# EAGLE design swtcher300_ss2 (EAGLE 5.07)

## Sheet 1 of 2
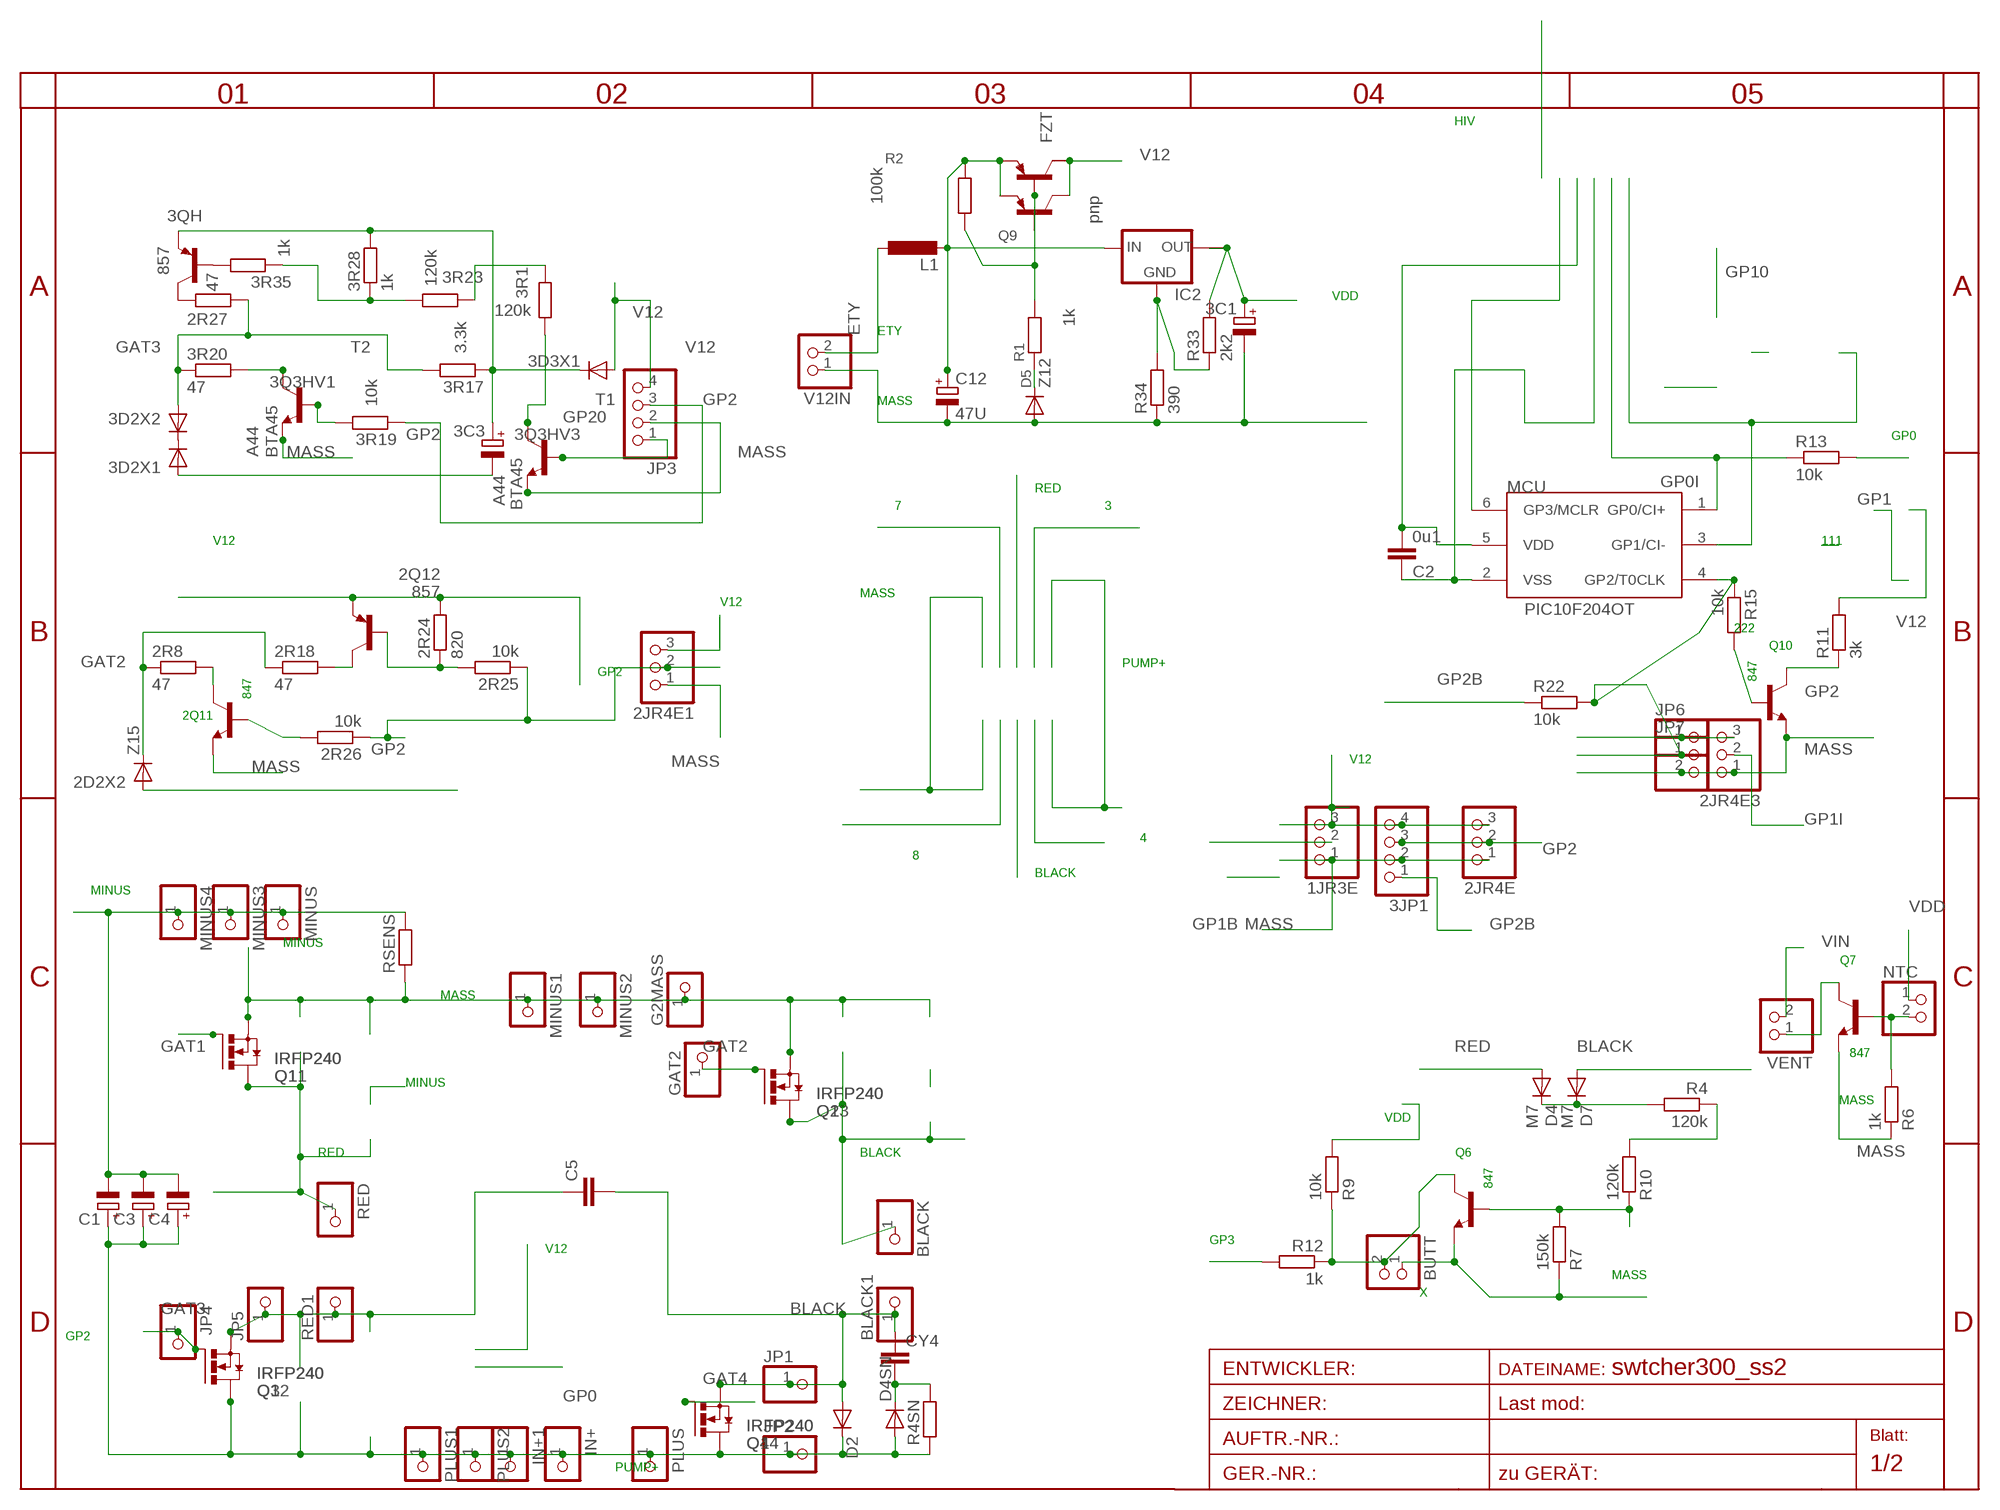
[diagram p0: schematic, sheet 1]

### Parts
1JR3E  PINHD-1X3  [1X03]
2D2X2  Z15  DIODE-MINIMELF  [MINIMELF]
2JR4E  PINHD-1X3  [1X03]
2JR4E1  PINHD-1X3  [1X03]
2JR4E3  PINHD-1X3  [1X03]
2Q11  847  BC847ALT1SMD  [SOT23]
2Q12  857  BC857ALT1SMD  [SOT23-BEC]
2R8  47  R-EU_R0805  [R0805]
2R18  47  R-EU_R0805  [R0805]
2R24  820  R-EU_R0805  [R0805]
2R25  10k  R-EU_R1206  [R1206]
2R26  10k  R-EU_R0805  [R0805]
2R27  47  R-EU_R0805  [R0805]
3C1  CPOL-EUD  [PANASONIC_D]
3C3  CPOL-EUD  [PANASONIC_D]
3D2X1  DIODE-MINIMELF  [MINIMELF]
3D2X2  DIODE-MINIMELF  [MINIMELF]
3D3X1  DIODE-SMA-DO214  [SMA-DO214AC]
3JP1  PINHD-1X4  [1X04]
3Q3HV1  BTA45  SMBTA45HV  [SOT23HV]
3Q3HV3  BTA45  SMBTA45HV  [SOT23HV]
3QH  857  BC857ALT1SMD  [SOT23-BEC]
3R1  120k  R-EU_R1206  [R1206]
3R17  3.3k  R-EU_R1206  [R1206]
3R19  10k  R-EU_R1206  [R1206]
3R20  47  R-EU_0207/10  [0207/10]
3R23  120k  R-EU_R1206  [R1206]
3R28  1k  R-EU_R0805  [R0805]
3R35  1k  R-EU_R0805  [R0805]
BLACK  PINHD-1X12MM3  [1X2MM3]
BLACK1  PINHD-1X12MM3  [1X2MM3]
BUTT  PINHD-1X2STR  [1X02]
C1  CPOL-EUE5-13  [E5-13]
C2  0u1  C-EUC0805  [C0805]
C3  CPOL-EUE5-13  [E5-13]
C4  CPOL-EUE5-13  [E5-13]
C5  C-EU075-032X103  [C075-032X103]
C12  47U  CPOL-EUSMCA  [SMC_A]
CY4  CXXC10B5  [XC10B5]
D2  DIODE-SMC  [SMC]
D4  M7  1N4004DO41-10  [DO41-10]
D4SN  DIODE-P1-10  [P1-10]
D5  Z12  DIODE-MINIMELF  [MINIMELF]
D7  M7  1N4004DO41-10  [DO41-10]
FZT  FZT  FZT753SMD  [SOT223]
G2MASS  PINHD-1X11MM0  [1X1MM0]
GAT2  PINHD-1X11MM0  [1X1MM0]
IC2  AP1117  [SOT223]
IN+  PINHD-1X12MM3  [1X2MM3]
IN+1  PINHD-1X12MM3  [1X2MM3]
JP1  PINHD-1X11MM0  [1X1MM0]
JP2  PINHD-1X11MM0  [1X1MM0]
JP3  PINHD-1X4  [1X04]
JP4  PINHD-1X11MM0  [1X1MM0]
JP5  PINHD-1X11MM0  [1X1MM0]
JP6  PINHD-1X11X0.4  [1X01]
JP7  PINHD-1X2STR  [1X02]
L1  L-EU0204/5  [0204/5]
MCU  PIC10F204OT  [SOT23-6]
MINUS  PINHD-1X12MM3  [1X2MM3]
MINUS1  PINHD-1X12MM3  [1X2MM3]
MINUS2  PINHD-1X12MM3  [1X2MM3]
MINUS3  PINHD-1X12MM3  [1X2MM3]
MINUS4  PINHD-1X12MM3  [1X2MM3]
NTC  PINHD-1X2STR  [1X02]
PLUS  PINHD-1X12MM3  [1X2MM3]
PLUS1  PINHD-1X12MM3  [1X2MM3]
PLUS2  PINHD-1X12MM3  [1X2MM3]
Q1  IRFP240  [TO247BV]
Q2  IRFP240  [TO247BV]
Q3  IRFP240  [TO247BV]
Q4  IRFP240  [TO247BV]
Q6  847  BC847ALT1SMD  [SOT23]
Q7  847  BC847ALT1SMD  [SOT23]
Q9  pnp  BC857ALT1SMD  [SOT23-BEC]
Q10  847  BC847ALT1SMD  [SOT23]
Q11  IRFP240  [TO247BV]
Q12  IRFP240  [TO247BV]
Q13  IRFP240  [TO247BV]
Q14  IRFP240  [TO247BV]
R1  1k  R-EU_R0805  [R0805]
R2  100k  R-EU_R0805  [R0805]
R4  120k  R-EU_R1210  [R1210]
R4SN  R-EU_0207/10  [0207/10]
R6  1k  R-EU_R0805  [R0805]
R7  150k  R-EU_R0805  [R0805]
R9  10k  R-EU_R0805  [R0805]
R10  120k  R-EU_R1210  [R1210]
R11  3k  R-EU_R0805  [R0805]
R12  1k  R-EU_R0805  [R0805]
R13  10k  R-EU_R0805  [R0805]
R15  10k  R-EU_R0805  [R0805]
R22  10k  R-EU_R1206  [R1206]
R33  2k2  R-EU_R0805  [R0805]
R34  390  R-EU_R0805  [R0805]
RED  PINHD-1X12MM3  [1X2MM3]
RED1  PINHD-1X12MM3  [1X2MM3]
RSENS  R-EU_0204/7  [0204/7]
T1  A44  2N2222-NPN-TO92-EBC  [TO92-EBC]
T2  A44  2N2222-NPN-TO92-EBC  [TO92-EBC]
V12IN  PINHD-1X2STR  [1X02]
VENT  PINHD-1X2STR  [1X02]

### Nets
222: Q10.1(B) R15.2
BLACK: BLACK1.1 BLACK.1 C5.2 CY4.1 D2.A D7.A JP1.1 Q2.D Q4.S Q13.D Q14.S
BTRAP+: 3C3.+ 3D3X1.K(C) 3QH.E 3R17.1 3R28.2
ETY: L1.1 V12IN.2
GAT1: Q1.G Q11.G
GAT2: 2D2X2.C 2R8.1 2R18.1 GAT2.1 Q2.G Q13.G
GAT3: 2R27.2 3D2X2.A 3R17.2 3R20.1 JP4.1 Q3.G Q12.G
GAT4: Q4.G Q14.G
GP0: R13.2
GP0I: MCU.1(GP0/CI+) R13.1 ; also sheet 2
GP1I: 2JR4E3.2 MCU.3(GP1/CI-) ; also sheet 2
GP2: 2JR4E1.2 2JR4E.2 2R25.1 2R26.1 3JP1.3 3R19.1 JP3.3 Q10.3(C) R11.1
GP2B: 3JP1.1 3Q3HV3.1(B) JP3.1 R22.1 T1.B
GP2I: 1JR3E.2 JP7.1 MCU.4(GP2/T0CLK) R15.1 R22.2 ; also sheet 2
GP3: MCU.6(GP3/MCLR) R12.2 ; also sheet 2
GP20: 3Q3HV3.3(C) 3R1.1 T1.C
HVC1: 3Q3HV1.3(C) 3R20.2 T2.C
MASS: 1JR3E.1 2D2X2.A 2JR4E1.1 2JR4E3.1 2JR4E.1 2Q11.2(E) 3C1.- 3JP1.2 3Q3HV1.2(E) 3Q3HV3.2(E) BUTT.1 C2.1 C12.- D5.A G2MASS.1 JP3.2 JP7.2 MCU.2(VSS) MINUS1.1 MINUS2.1 Q1.S Q2.S Q6.2(E) Q7.2(E) Q10.2(E) Q11.S Q13.S R6.1 R7.1 R34.1 RSENS.1 T1.E T2.E V12IN.1 ; also sheet 2
MINUS: C1.- C3.- C4.- MINUS3.1 MINUS4.1 MINUS.1 RSENS.2
N$1: D4.C D7.C R4.2
N$2: FZT.1(B) Q9.B R1.2 R2.1
N$3: D5.C R1.1
N$4: 2Q11.3(C) 2R8.2
N$5: Q6.1(B) R7.2 R10.1
N$6: 2Q12.B 2R24.1 2R25.2
N$7: R4.1 R10.2
N$8: 2Q12.C 2R18.2
N$9: NTC.2 Q7.1(B) R6.2
N$10: Q7.3(C) VENT.1
N$11: 3R1.2 3R23.2
N$12: 3Q3HV1.1(B) 3R19.2 T2.B
N$13: 2R27.1 3QH.C
N$17: 3QH.B 3R35.2
N$18: 3R23.1 3R28.1 3R35.1
N$21: 3D2X1.C 3D2X2.C
N$22: 2Q11.1(B) 2R26.2
N$30: IC2.1(GND) R33.1 R34.2
PUMP+: C1.+ C3.+ C4.+ D2.C D4SN.A IN+1.1 IN+.1 JP2.1 PLUS1.1 PLUS2.1 PLUS.1 Q3.D Q4.D Q12.D Q14.D R4SN.1 ; also sheet 2
RED: 3C3.- 3D2X1.A C5.1 D4.A JP5.1 Q1.D Q3.S Q11.D Q12.S RED1.1 RED.1
SNUB2: CY4.2 D4SN.C R4SN.2
V12: 1JR3E.3 2JR4E1.3 2JR4E3.3 2JR4E.3 2Q12.E 2R24.2 3D3X1.A 3JP1.4 FZT.2(C) JP3.4 JP6.1 Q9.C R11.2
VDD: 3C1.+ C2.2 IC2.2(OUT) IC2.4(TAB) MCU.5(VDD) NTC.1 R9.2 R33.2 ; also sheet 2
VIN: C12.+ FZT.3(E) IC2.3(IN) L1.2 Q9.E R2.2 VENT.2
X: BUTT.2 Q6.3(C) R9.1 R12.1
Unconnected: FZT.4(C/)

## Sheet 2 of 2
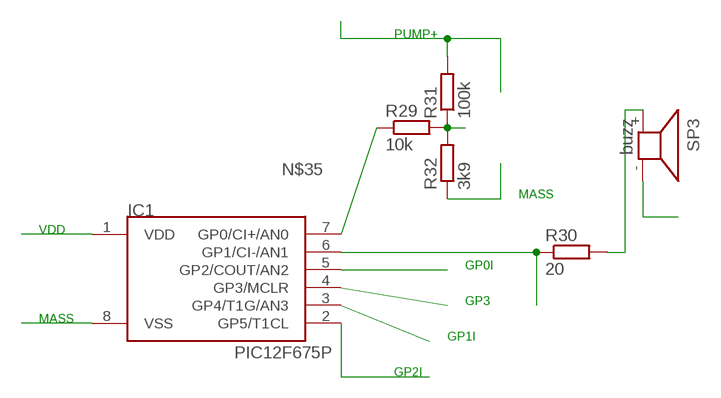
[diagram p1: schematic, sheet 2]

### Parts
IC1  PIC12F675P  [DIL8]
R29  10k  R-EU_R0805  [R0805]
R30  20  R-EU_R0805  [R0805]
R31  100k  R-EU_0207/25  [0207/25]
R32  3k9  R-EU_R0805  [R0805]
SP3  buzz  KSS12017MM  [KSS1202]

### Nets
GP0I: IC1.5(GP2/COUT/AN2) ; also sheet 1
GP1I: IC1.3(GP4/T1G/AN3) ; also sheet 1
GP2I: IC1.2(GP5/T1CL) ; also sheet 1
GP3: IC1.4(GP3/MCLR) ; also sheet 1
MASS: IC1.8(VSS) R32.1 SP3.- ; also sheet 1
N$24: R30.2 SP3.+
N$31: IC1.6(GP1/CI-/AN1) R30.1
N$34: R29.2 R31.1 R32.2
N$35: IC1.7(GP0/CI+/AN0) R29.1
PUMP+: R31.2 ; also sheet 1
VDD: IC1.1(VDD) ; also sheet 1

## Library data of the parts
1JR3E 2JR4E 2JR4E1 2JR4E3 = pinhead:PINHD-1X3: PIN HEADER
2D2X2 3D2X1 3D2X2 3D3X1 D2 D4SN D5 = diode:DIODE-: DIODE
2Q11 Q6 Q7 Q10 = transistor-npn:BC847*: NPN Transistor
2Q12 3QH Q9 = transistor-pnp:BC857*: PNP Transistror
2R8 2R18 2R24-2R27 3R1 3R17 3R19 3R20 3R23 3R28 3R35 R4 R4SN R6 R7 R9 R10 R12 RSENS = rcl:R-EU_: RESISTOR, European symbol
3C1 3C3 C1 C3 C4 = rcl:CPOL-EU: POLARIZED CAPACITOR, European symbol
3JP1 JP3 = pinhead:PINHD-1X4: PIN HEADER
3Q3HV1 3Q3HV3 = transistor-npn:SMBTA45
BLACK BLACK1 G2MASS GAT2 IN+ IN+1 JP1 JP2 JP4-JP6 MINUS MINUS1-MINUS4 PLUS PLUS1 PLUS2 RED RED1 = pinhead:PINHD-1X1: PIN HEADER
BUTT JP7 NTC V12IN VENT = pinhead:PINHD-1X2: PIN HEADER
C2 C5 = rcl:C-EU: CAPACITOR, European symbol
C12 = rcl-2:CPOL-EU: POLARIZED CAPACITOR, European symbol
CY4 = rcl:CX: X CAPACITOR
D4 D7 = diode:1N4004: DIODE
FZT = transistor-pnp:FZT753SMD: PNP Transistor
IC1 = microchip-5:PIC12F6*: uPC nW 1k Program Flash memory 2x Timer Comparator 10b A/D converter/ 4xIN
IC2 = v-reg:AP1117
L1 = rcl:L-EU: INDUCTOR, European symbol
MCU = microchip-3:PIC10F2*: uPC nW 0,25/0,5k Program Flash memory Comparator
Q1-Q4 Q11-Q14 = transistor-power:IRFP240: HEXFET Power MosFet Source: http://www.irf.com/
R1 R2 R11 R13 R15 R22 R29-R34 = rcl-2:R-EU_: RESISTOR, European symbol
SP3 = buzzer:KSS1201: SPEAKER
T1 T2 = transistor-neu-to92:*-NPN-: NPN Transistror

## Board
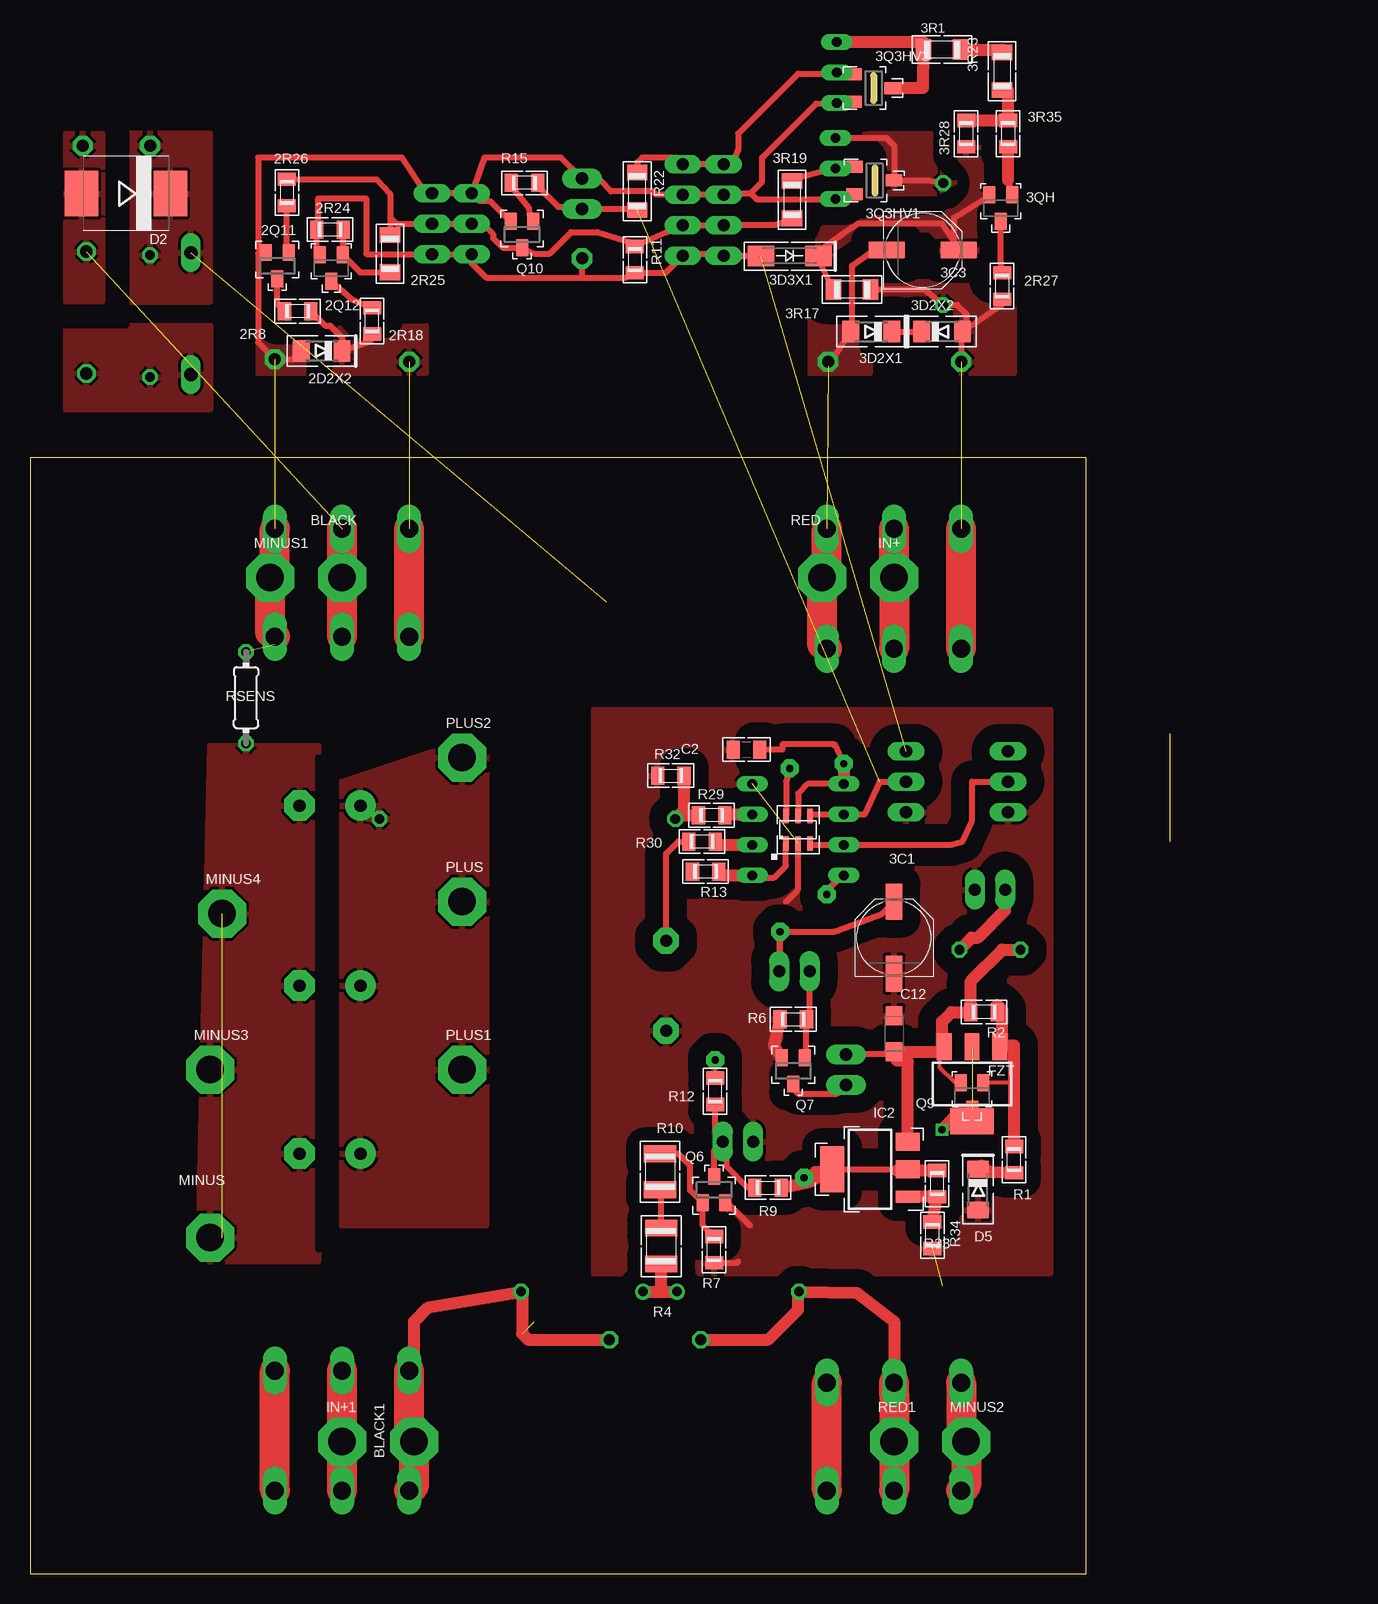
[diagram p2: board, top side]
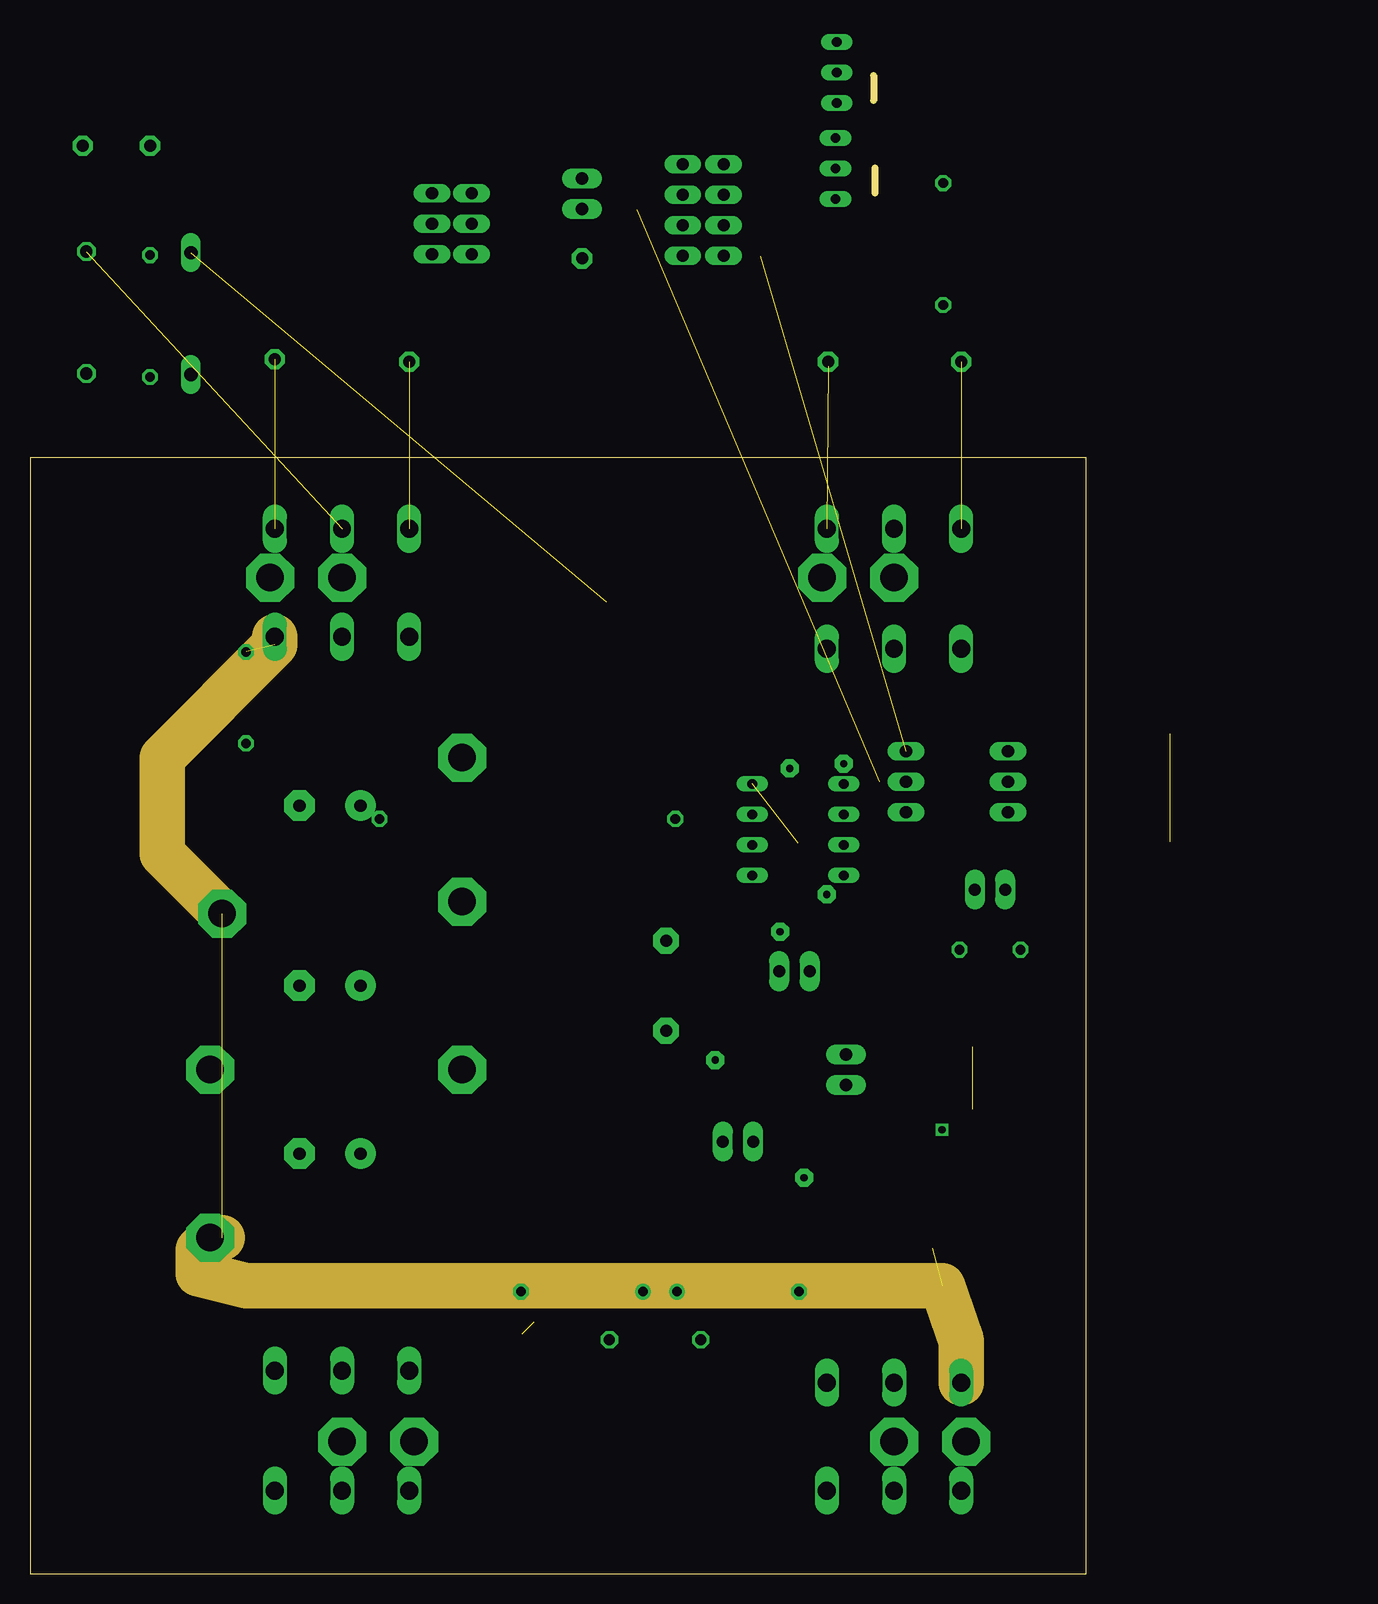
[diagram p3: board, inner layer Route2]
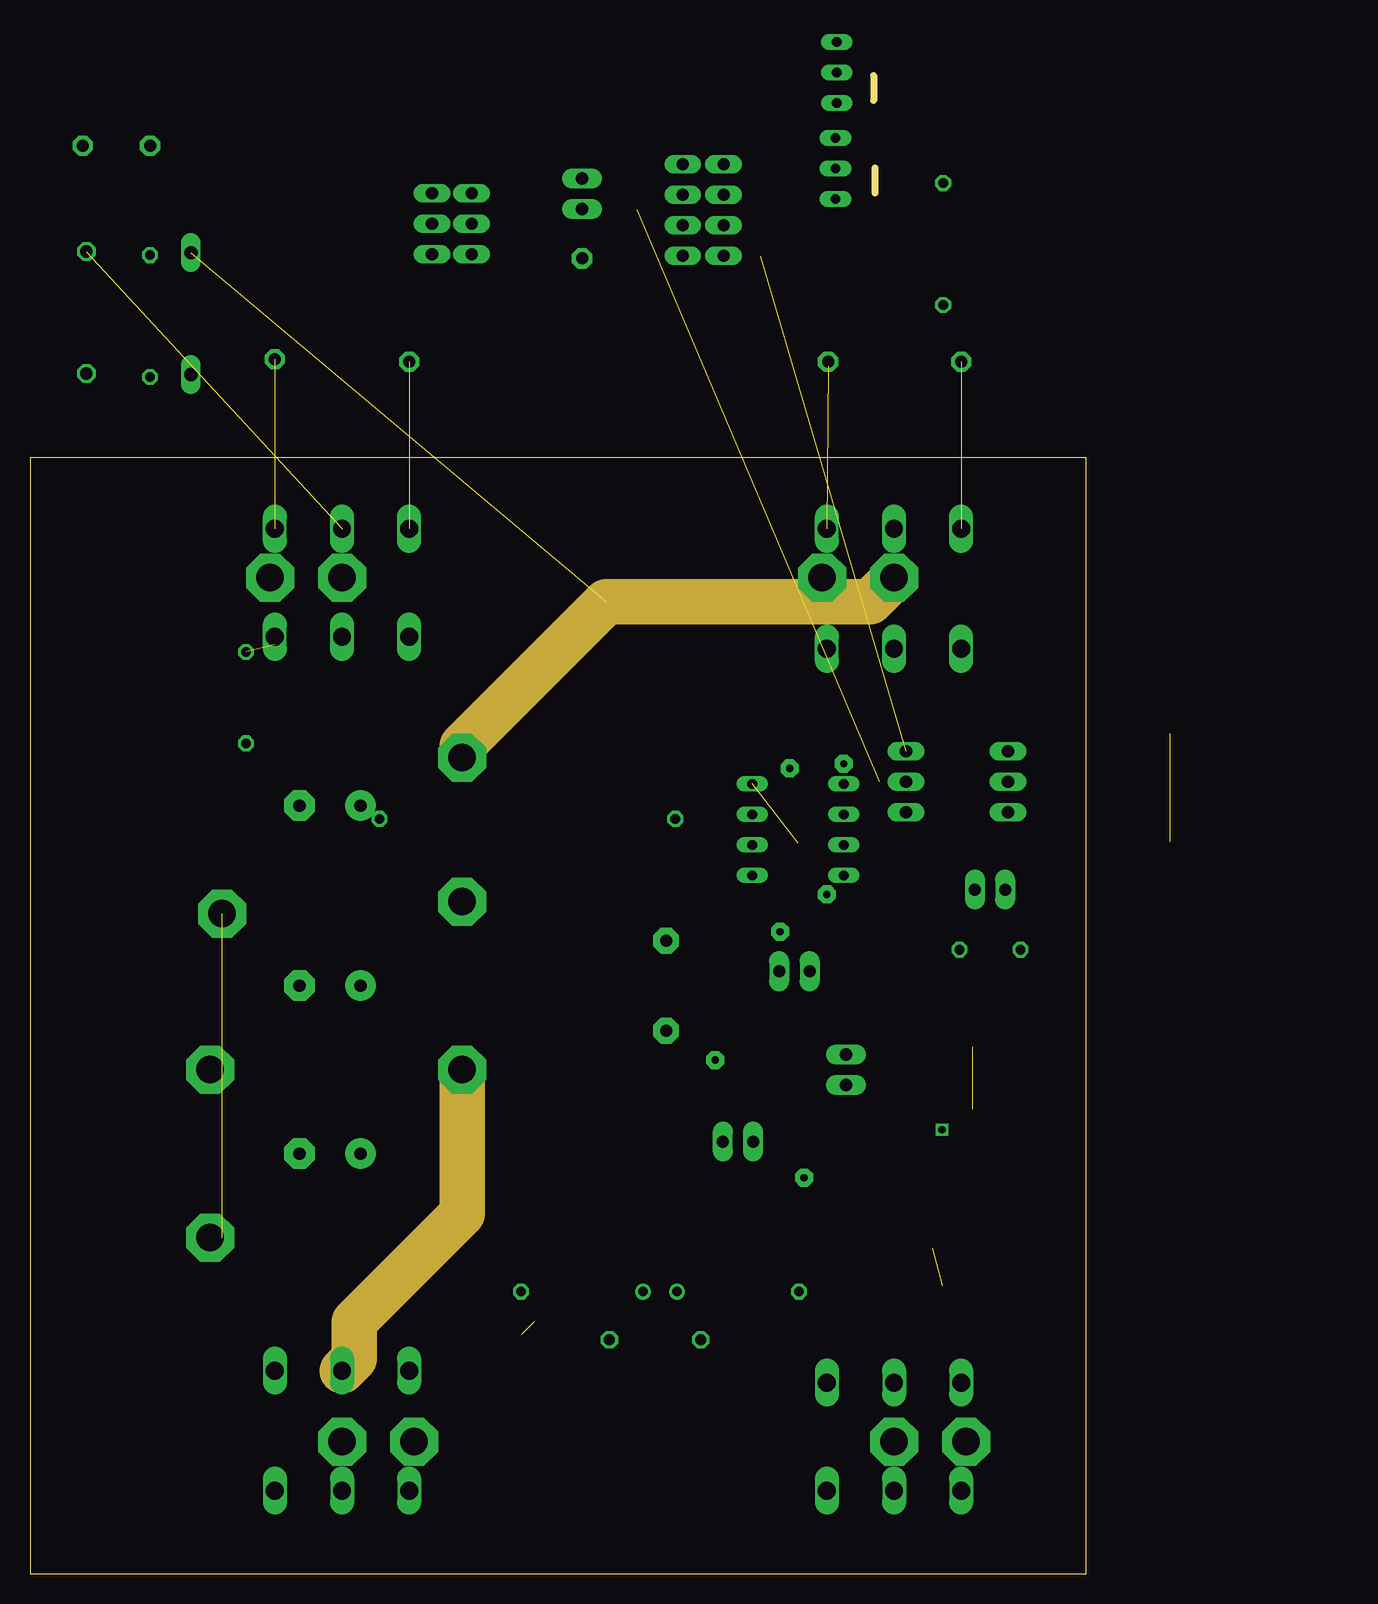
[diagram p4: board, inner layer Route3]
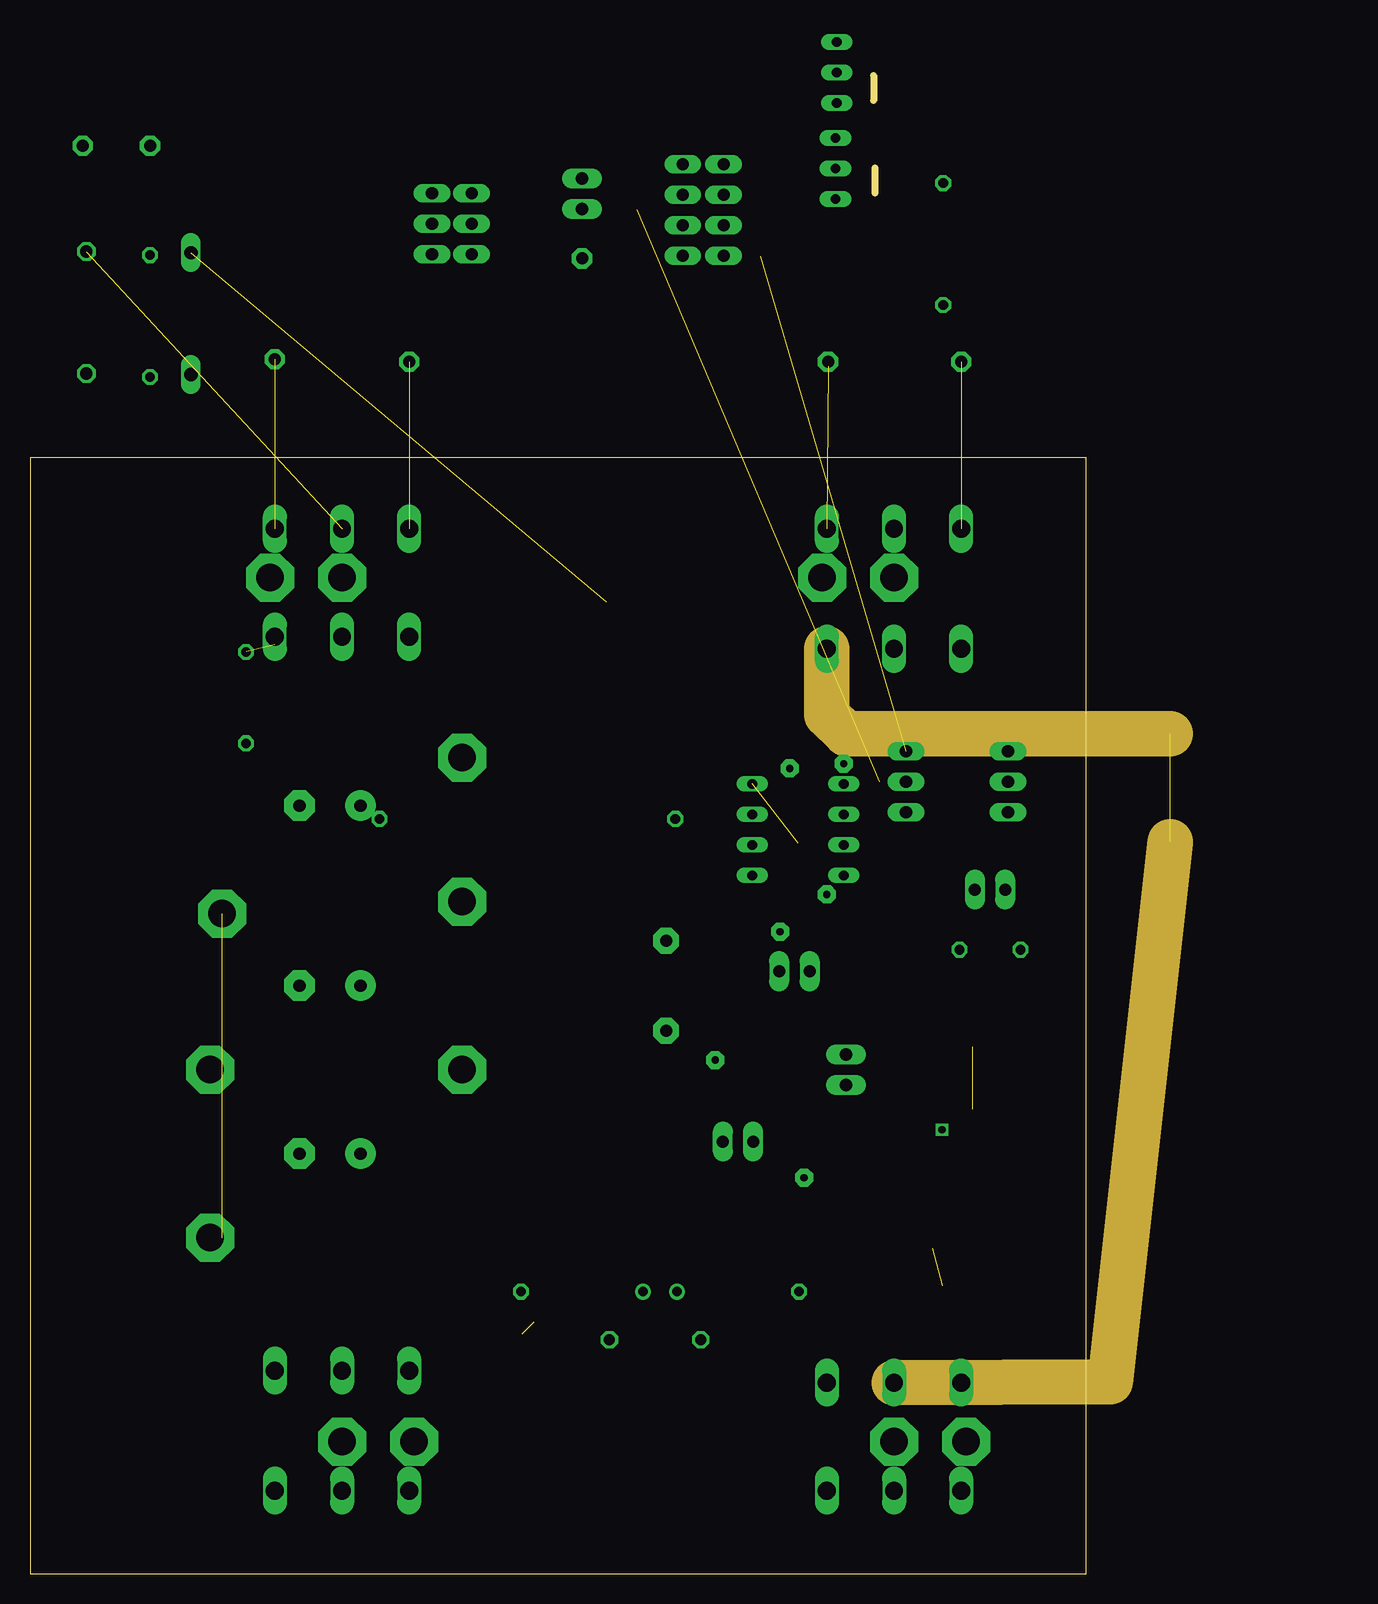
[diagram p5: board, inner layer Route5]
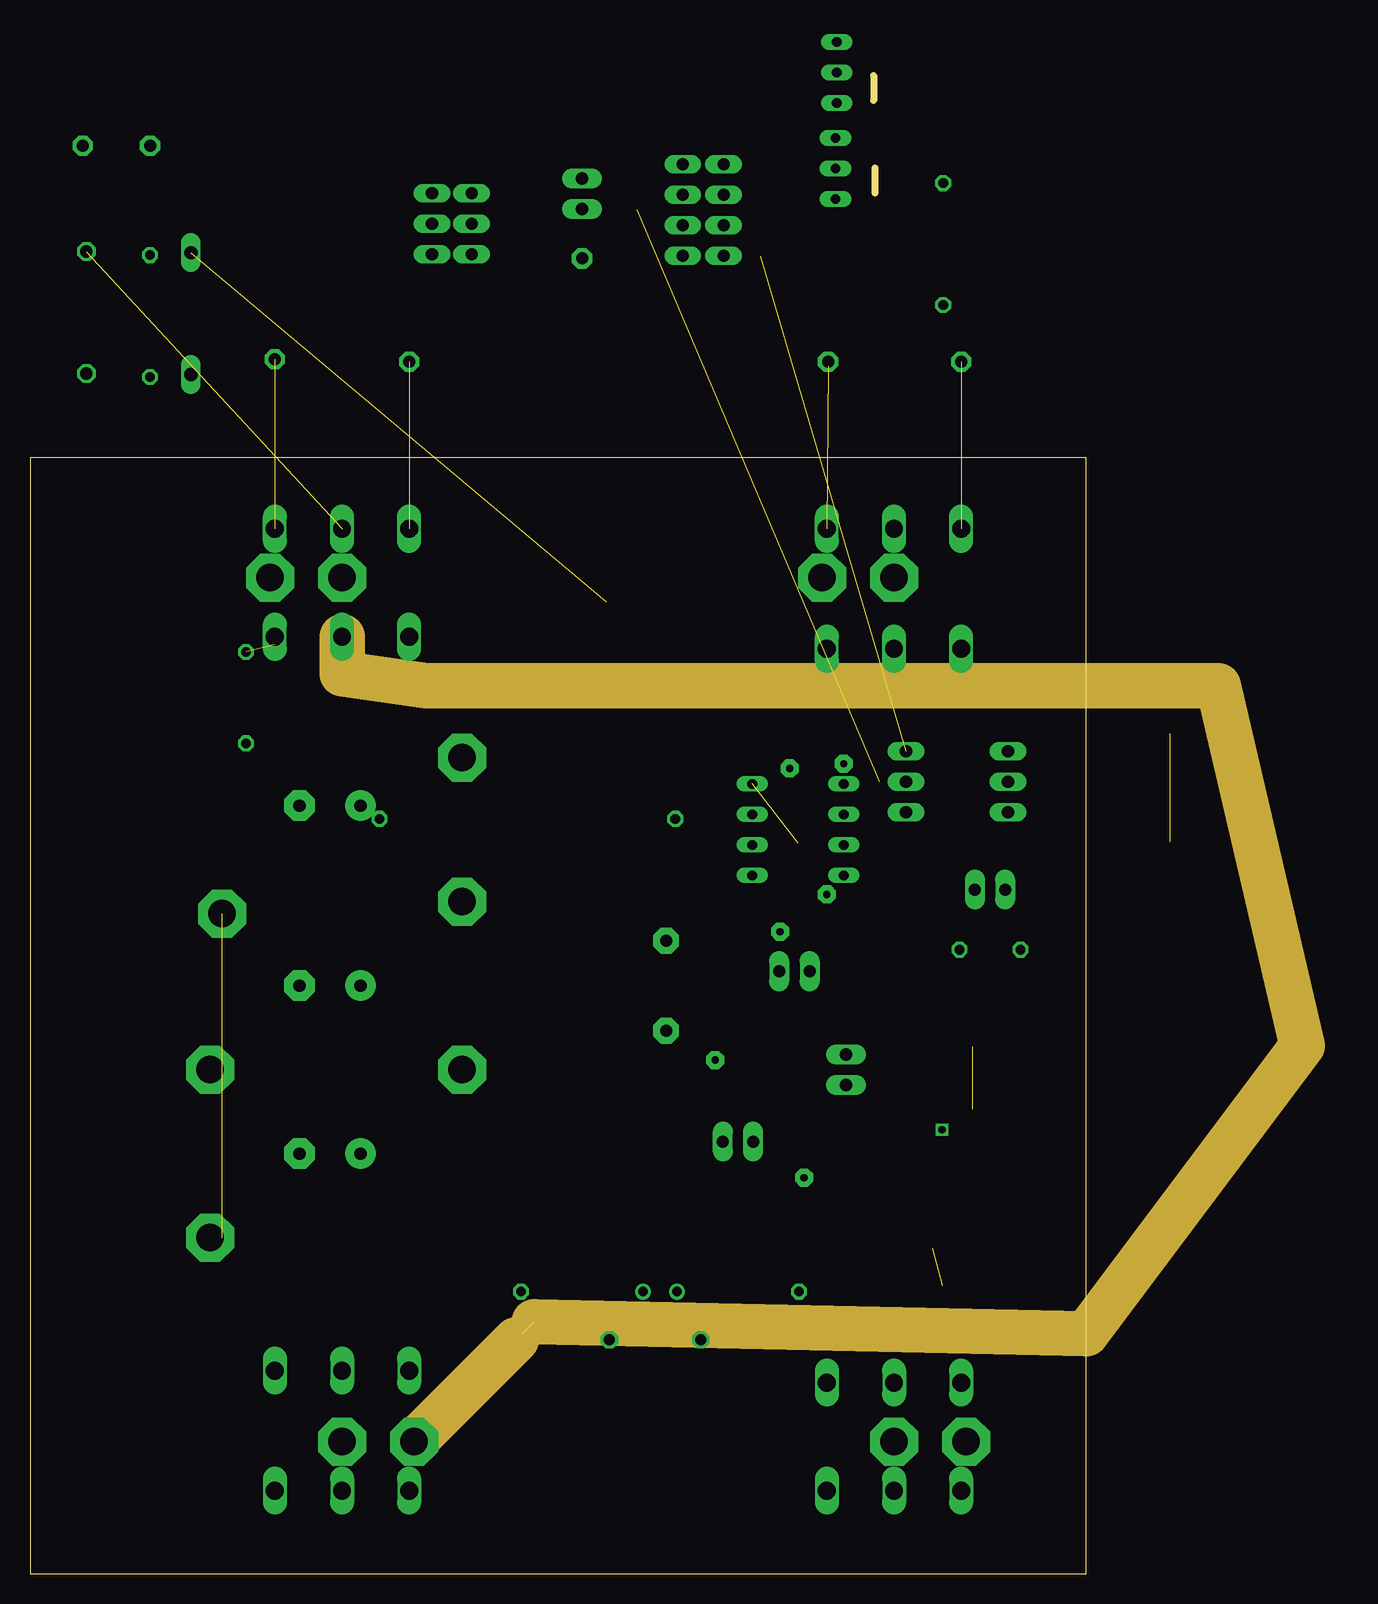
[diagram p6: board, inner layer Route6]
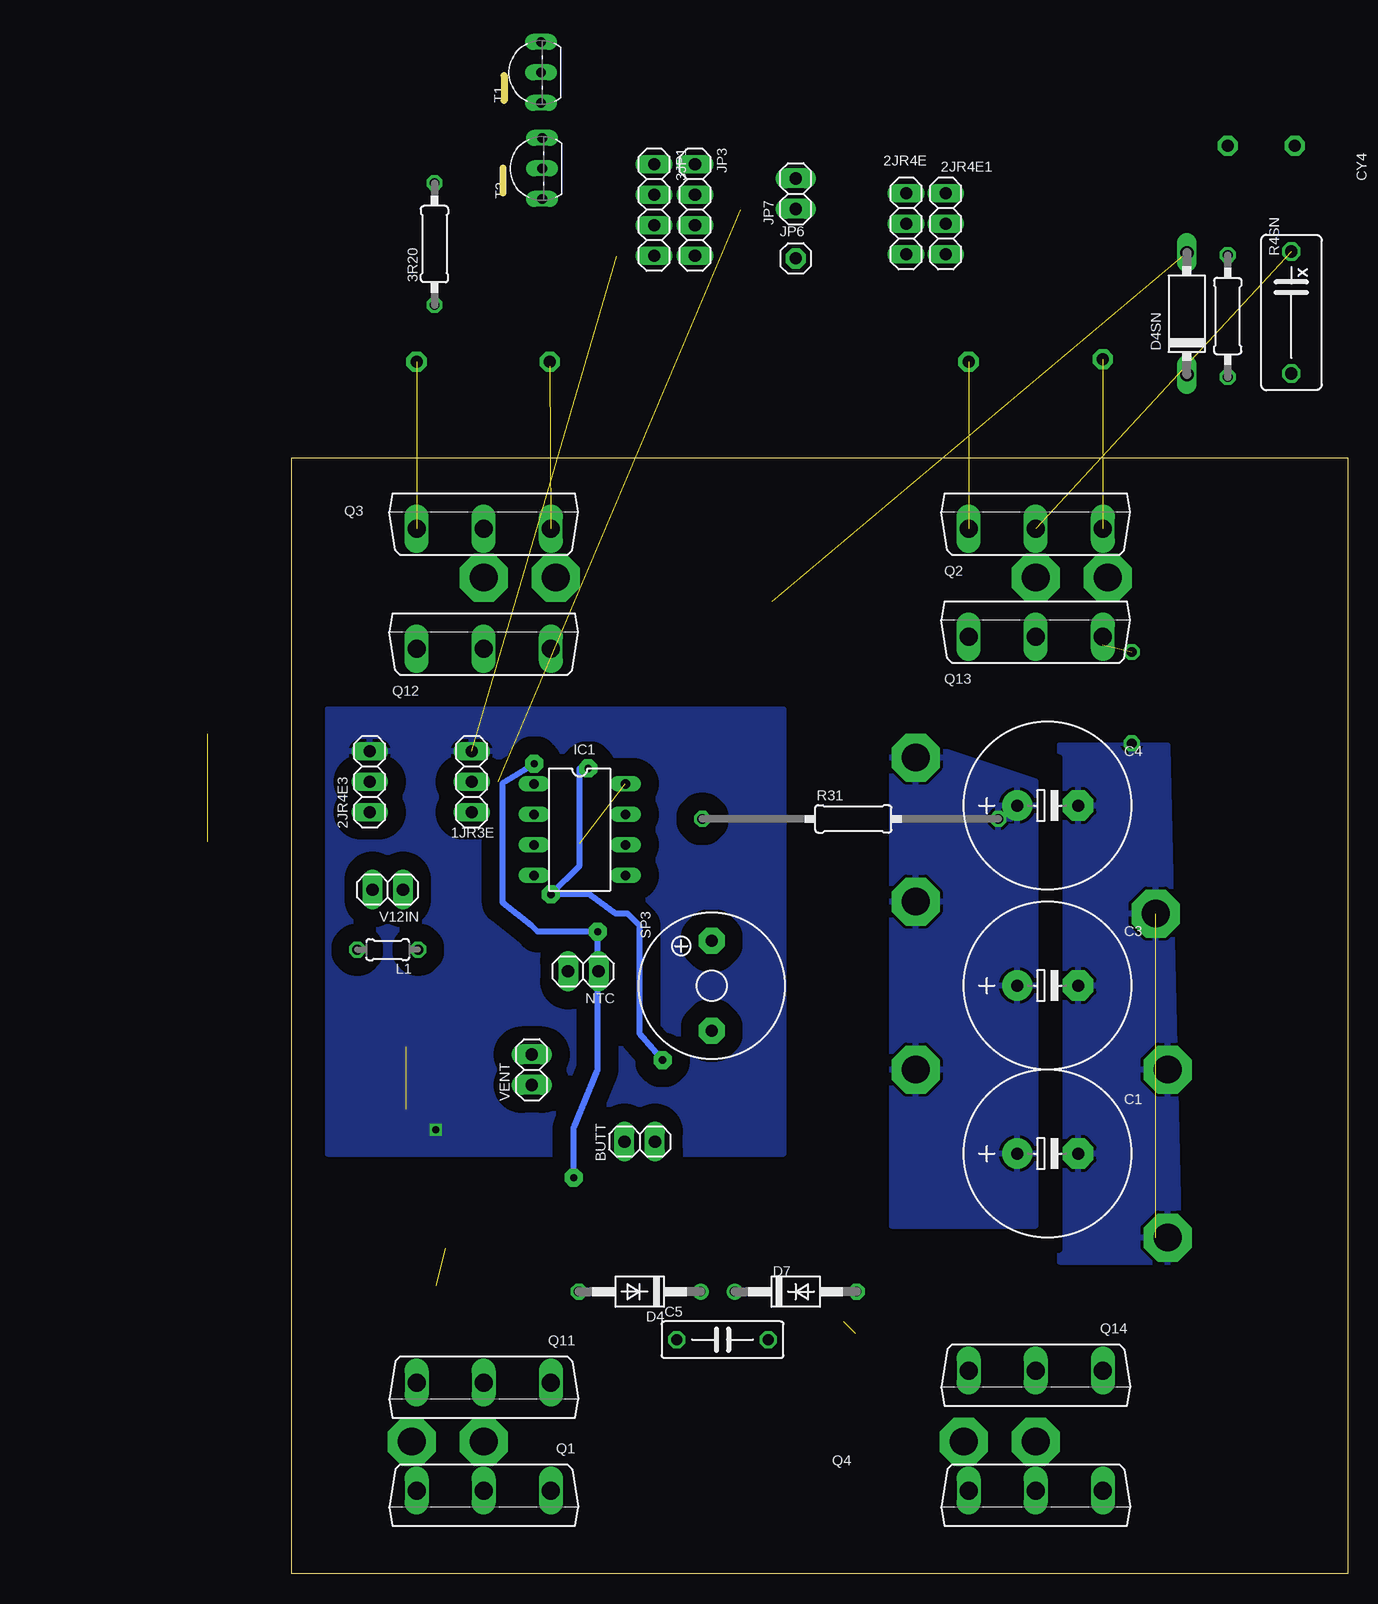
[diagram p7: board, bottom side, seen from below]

Size 88 x 93 mm. Coordinates in mm from the lower left corner, seen from the top.
Outline: 0,0 88,0 88,93 0,93 0,0
Copper layers (1*16): Top 0.035mm / dielectric 1.5mm / Bottom 0.035mm
Design rules "default *": minimum track width 10mil, minimum drill 20mil, track to track 8mil, track to pad 8mil, pad to pad 8mil, via to via 8mil, smd to smd 8mil, copper to edge 40mil, drill to drill 8mil, minimum pad ring 10mil, minimum via ring 8mil, stop-mask expansion 4mil, vias tented up to drill 0mil, thermal gap 10mil

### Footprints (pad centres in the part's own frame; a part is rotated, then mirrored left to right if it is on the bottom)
1X03 = drill 1.016 long: 1 -2.54,0; 2 0,0; 3 2.54,0
MINIMELF = smd 1.4 x 1.8: A 1.7,0; C -1.7,0
SOT23 = smd 1 x 1.4: 1 -0.95,-1.1; 2 0.95,-1.1; 3 0,1.1
SOT23-BEC = smd 1 x 1.4: B -0.95,-1.1; C 0,1.1; E 0.95,-1.1
R0805 = smd 1.1 x 1.5: 1 -1.1,0; 2 1.1,0
R1206 = smd 1.3 x 1.7: 1 -1.55,0; 2 1.55,0
PANASONIC_D = smd 3 x 1.4: + 3,0; - -3,0
SMA-DO214AC = smd 2.2 x 1.7: A 2.4,0; K -2.4,0
1X04 = drill 1.016 long: 1 -3.81,0; 2 -1.27,0; 3 1.27,0; 4 3.81,0
SOT23HV = smd 1 x 1.4: 1 -1.15,-1.7; 2 1.15,-1.7; 3 0,1.6
0207/10 = drill 0.813 octagon: 1 -5.08,0; 2 5.08,0
1X2MM3 = drill 2.3 pad 4 octagon: 1 0,0
1X02 = drill 1.016 pad 1.676 long: 1 -1.27,0; 2 1.27,0
E5-13 = drill 1.016 pad 2.54 round: + -2.54,0 | drill 1.016 pad 2.54 octagon: - 2.54,0
C0805 = smd 1.1 x 1.5: 1 -1.1,0; 2 1.1,0
C075-032X103 = drill 0.914 octagon: 1 -3.81,0; 2 3.81,0
SMC_A = smd 1.6 x 1.4: + -1.5,0; - 1.5,0
XC10B5 = drill 1.016 octagon: 1 -5.08,0; 2 5.08,0
SMC = smd 2.8 x 3.8: A 3.7,0; C -3.7,0
DO41-10 = drill 0.8 octagon: A 5.08,0 | drill 0.8 round: C -5.08,0
P1-10 = drill 1.118 long: A 5.08,0; C -5.08,0
SOT223 = smd 1.219 x 2.235: 1 -2.311,-3.099; 2 0,-3.099; 3 2.311,-3.099 | smd 3.6 x 2.2: 4 0,3.099
1X1MM0 = drill 1 pad 1.676 octagon: 1 0,0
DIL8 = drill 0.8 long: 1 -3.81,-3.81; 2 -1.27,-3.81; 3 1.27,-3.81; 4 3.81,-3.81; 5 3.81,3.81; 6 1.27,3.81; 7 -1.27,3.81; 8 -3.81,3.81
SOT223' = smd 1 x 2: 1 -2.3,-3.15 | smd 1.5 x 2: 2 0,-3.15; 3 2.3,-3.15 | smd 3.8 x 2: 4 0,3.15
1X01 = drill 1 pad 1.676 octagon: 1 0,0
0204/5 = drill 0.813 octagon: 1 -2.54,0; 2 2.54,0
SOT23-6 = smd 0.45 x 1.2: 1 -1.016,-1.15; 2 0,-1.15; 3 1.016,-1.15; 4 1.016,1.15; 5 0,1.15; 6 -1.016,1.15
TO247BV = drill 1.499 long: D 0,-2.921; G -5.588,-2.921; S 5.588,-2.921
R1210 = smd 1.4 x 2.7: 1 -1.5,0; 2 1.5,0
0207/25 = drill 0.813 octagon: 1 -12.58,0; 2 12.08,0
0204/7 = drill 0.813 octagon: 1 -3.81,0; 2 3.81,0
KSS1202 = drill 1 pad 2.159 octagon: + 3.75,0; - -3.75,0
TO92-EBC = drill 0.813 long: B 0,-1.27; C 2.54,-1.27; E -2.54,-1.27

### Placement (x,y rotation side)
1JR3E  73,66 90 bottom
2D2X2  24.3,101.9 180 top  (outside the outline)
2JR4E  36.8,112.5 270 bottom  (outside the outline)
2JR4E1  33.5,112.5 270 bottom  (outside the outline)
2JR4E3  81.5,66 90 bottom
2Q11  20.6,109 180 top  (outside the outline)
2Q12  25.1,108.8 180 top  (outside the outline)
2R8  22.3,105.2 180 top  (outside the outline)
2R18  28.5,104.4 90 top  (outside the outline)
2R24  25,112 180 top  (outside the outline)
2R25  30,110 270 top  (outside the outline)
2R26  21.4,115.1 270 top  (outside the outline)
2R27  81,107.3 270 top  (outside the outline)
3C1  72,53 90 top
3C3  74.4,110.3 0 top  (outside the outline)
3D2X1  70.1,103.5 180 top  (outside the outline)
3D2X2  76,103.5 0 top  (outside the outline)
3D3X1  63.3,109.8 180 top  (outside the outline)
3JP1  57.8,113.65 270 bottom  (outside the outline)
3Q3HV1  70.4,116.1 270 top  (outside the outline)
3Q3HV3  70.3,123.8 270 top  (outside the outline)
3QH  80.9,113.8 180 top  (outside the outline)
3R1  76,127 0 top  (outside the outline)
3R17  68.5,107 0 top  (outside the outline)
3R19  63.5,114.5 90 top  (outside the outline)
3R20  76.1,110.8 90 bottom  (outside the outline)
3R23  81,125.2 90 top  (outside the outline)
3R28  78,120 270 top  (outside the outline)
3R35  81.5,120 270 top  (outside the outline)
BLACK  26,83 0 top
BLACK1  32,11 90 top
BUTT  59,36 0 bottom
C1  25,35 0 bottom
C2  59.7,68.68 0 top
C3  25,49 0 bottom
C4  25,64 0 bottom
C5  52.1,19.5 0 bottom
C12  72,45 90 top
CY4  not placed on the board
D2  not placed on the board
D4  59,23.5 180 bottom
D4SN  not placed on the board
D5  79,32 270 top
D7  46,23.5 0 bottom
FZT  78.5,40.8 180 top
G2MASS  20.4,101.2 0 top  (outside the outline)
GAT2  not placed on the board
IC1  64,62 270 bottom
IC2  AP1117  [SOT223']  70,33.7 90 top
IN+  72,83 0 top
IN+1  26,11 0 top
JP1  not placed on the board
JP2  not placed on the board
JP3  54.4,113.65 270 bottom  (outside the outline)
JP4  77.6,101 180 top  (outside the outline)
JP5  66.5,101 180 top  (outside the outline)
JP6  46,109.6 0 bottom  (outside the outline)
JP7  46,115 90 bottom  (outside the outline)
L1  80,52 180 bottom
MCU  64,62 0 top
MINUS  15,28 0 top
MINUS1  20,83 0 top
MINUS2  78,11 0 top
MINUS3  15,42 0 top
MINUS4  16,55 0 top
NTC  63.7,50.2 180 bottom
PLUS  36,56 0 top
PLUS1  36,42 0 top
PLUS2  36,68 0 top
Q1  72,4 180 bottom
Q2  26,90 0 bottom
Q3  72,90 0 bottom
Q4  26,4 180 bottom
Q6  57,32 0 top
Q7  63.6,41.9 180 top
Q9  78.5,39.8 180 top
Q10  41,111.6 180 top  (outside the outline)
Q11  72,13 180 bottom
Q12  72,80 0 bottom
Q13  26,81 0 bottom
Q14  26,14 180 bottom
R1  82,34.5 90 top
R2  79.5,46.8 180 top
R4  52.6,27.3 270 top
R4SN  not placed on the board
R6  63.6,46.2 0 top
R7  57,27 90 top
R9  61.5,32.17 0 top
R10  52.5,33.5 270 top
R11  50.4,109.5 270 top  (outside the outline)
R12  57.1,40.2 90 top
R13  56.3,58.5 180 top
R15  41.2,115.9 180 top  (outside the outline)
R22  50.6,115.2 270 top  (outside the outline)
R29  56.8,63.2 180 top
R30  56,61 180 top
R31  41.2,62.9 0 bottom
R32  53.4,66.5 0 top
R33  75.6,32.5 90 top
R34  75.2,28.2 90 top
RED  66,83 0 top
RED1  72,11 0 top
RSENS  18,73 270 top
SP3  53,49 90 bottom
T1  68.5,125.1 90 bottom  (outside the outline)
T2  68.4,117.1 90 bottom  (outside the outline)
V12IN  80,57 180 bottom
VENT  68,42 90 bottom

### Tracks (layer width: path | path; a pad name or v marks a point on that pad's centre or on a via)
222
  Top 0.5: R15.2 40.1,115.6 41.6,113.8 41.7,112.95 Q10.1
BLACK  (2 unrouted)
  Top 1: Q14.S 32,17.33 32,21 33.19,22.19 D7.A 41,23.42 41,20 41.5,19.5 C5.2
  Top 2.5: Q2.D BLACK.1 Q13.D | Q14.S 31.59,11.41 BLACK1.1 32,7.33 Q4.S
  Route6 3.81: Q13.D 26,75 33,74 99,74 106,44 88,20 42,21 | BLACK1.1 40.5,19.5
  pour Top (isolate 2): 3,120 6,120 6,106 3,106
BTRAP+
  Top 0.5: 65.45,110 67.8,111.7 69,112.5 76,112.5 77,111 | 65.45,110 3R17.1 | 77,111 77,110.7 3C3.+ | 3R28.2 78.3,118.7 | 3QH.E 80,114.85 77,113 77,111 | 3D3X1.K 66.25,109.8 65.45,110
  pour Top (isolate 1.5, rank 2): 65,110 65,111 67,113 76,113 77,114 77,118 78,119 79,119 80,118 80,111 79,110 76,110 76,111 75,112 69,112 68,111 68,110 67,109
ETY
  Top 1: V12IN.2 81.27,55.27 79,53 78.46,53 L1.1
GAT1
  Top 2.5: Q1.G Q11.G
GAT2  (1 unrouted)
  Top 0.5: 2R8.1 24.6,104 25,104 26,103 2D2X2.C 28.3,102.7 2R18.1
  Top 2.5: Q13.G Q2.G
  pour Top (isolate 2): 25,103 26,104 33,104 33,100 25,100
GAT3  (1 unrouted)
  Top 0.5: 2R27.2 81,105.8 3D2X2.A | 3R17.2 74.55,107 3R20.1 77.28,105.72 78,105 78,103.8 3D2X2.A | JP4.1 77.6,103.4 3D2X2.A
  Top 2.5: Q12.G Q3.G
  pour Top (isolate 2, rank 2): 70,107.7 79,107.7 81,106 82,106 82,100 77,100 77,105 71,105 70,106
GAT4
  Top 2.5: Q4.G Q14.G
GP0I
  Top 0.5: MCU.1 62.98,59.02 63,59 62,58 60.38,58 IC1.5
  Top 1: IC1.5 57.71,58.19 R13.1
GP1I
  Top 0.5: 2JR4E3.2 78.5,66 78.5,62.8 77.7,61 76.73,60.73 IC1.3 65.14,60.73 MCU.3
GP2
  Top 0.5: 3R19.1 62.55,112.55 62,112.4 58.18,112.4 3JP1.3 JP3.3 53.03,111.78 R11.1 50.15,110.9 47.3,111.8 45.1,111.8 43.3,110 42,110 Q10.3 39.4,110.5 38.6,111.3 38.6,111.6 37.7,112.5 2JR4E.2 2JR4E1.2 30.5,112.5 30,113 | 2R26.1 28.9,116.2 30,115 30,113 | 30,113 2R25.1
GP2B
  Top 0.5: R22.1 50.6,117.6 51,118 53.86,118 JP3.1 3JP1.1 58.46,117.46 59,118.7 59,120 64,125 67.13,125 T1.B 68.45,125.1 3Q3HV3.1
GP2I  (1 unrouted)
  Top 0.5: R15.1 42.3,115.6 44,113.9 45.83,113.9 JP7.1 50.52,113.73 R22.2 | 1JR3E.2 70.8,66 69.58,63.3 IC1.2 65.14,63.27 MCU.4
GP3  (via drill 0.6 pad 1.5)
  Top 0.35: R12.2 v57.1,42.8
  Top 0.5: IC1.4 66.39,56.99 v66.4,56.6 | v63.3,67.1 63,66 63,63.17 MCU.6
  Bottom 0.5: v63.3,67.1 64,67.1 64,64.8 64,59 v66.4,56.6 63.2,56.6 61,55 60,55 59,54 59,45 v57.1,42.8
GP20
  Top 1: T1.C 74.45,127.64 3R1.1 74.45,125.5 74.4,125.5 74.4,123.8 3Q3HV3.3
HVC1
  Top 0.5: T2.C 71.36,119.64 72,119 3Q3HV1.3 74.88,116.1 3R20.2
  pour Top (isolate 2, rank 2): 68,120 75,120 77,118 77,115 71,115 71,119 68,119
MASS  (5 unrouted)
  Top 0.5: 2JR4E.1 37.86,118 44.27,118 JP7.2 46.17,116.1 47.5,116.1 48.4,115.2 51.9,115.2 52.18,114.92 JP3.2 3JP1.2 57.88,115 60,115 | 19,110.5 19,118 31,118 32.96,115.04 2JR4E1.1 2JR4E.1 | 19,110.5 2Q11.2 | 19,110.5 19.55,110.55 19,110 19,102.6 G2MASS.1 21.9,101.2 2D2X2.A | 68,122.65 65.5,122.5 61,118 61,116 60,115 | 68,122.65 3Q3HV3.2 | Q10.2 40,112.7 38.3,114.4 37.44,114.4 2JR4E.1 | 60,115 60.1,115 60.6,114.5 67.07,114.5 T2.E 68.31,114.56 3Q3HV1.2 | T1.E 67.91,122.56 68,122.65 | Q6.2 58.1,30.9 60,29 | R7.1 58.9,25.9 59,26 | MCU.2 64,57 63,56
  Top 1: R6.1 62,44 Q7.2
  Top 2.5: Q2.S 20.41,83.41 MINUS1.1 20,78.49 Q13.S | Q11.S 77.59,11.41 MINUS2.1 78,7.33 Q1.S
  Route2 3.81: Q13.S 20.41,77.41 11,68 11,60 16,55 | Q11.S 77.59,19.41 76,24 18,24 14,25 14,27 15,28 16,28
  pour Top (isolate 1.5): 47,72 85,72 85,25 47,25
  pour Top (isolate 2, rank 2, no thermals): 19,105 22,105 23,104 23,100 19,100
MINUS
  pour Top (isolate 2, rank 2): 15,69 24,69 24,26 14,26
  pour Bottom (isolate 2, rank 2): 15,69 24,69 24,26 14,26
N$1
  Top 1: 52.6,23.5 R4.2 | D7.C 52.6,23.5 | 52.6,23.5 D4.C
N$2
  Top 0.35: Q9.B 81.9,40.9 82,41
  Top 1: R2.1 80.6,47.4 81,47 81,44.09 FZT.1 80.91,44 82,44 82,41 R1.2
N$3
  Top 1: R1.1 79.9,33.5 79.3,34 D5.C
N$4
  Top 0.5: 2Q11.3 20.6,105.8 2R8.2
N$5
  Top 0.5: R10.1 54,35 55,34 55,31.95 Q6.1 56.05,29.05 R7.2
N$6
  Top 0.5: 2R25.2 27.5,108.45 2Q12.B 26.1,109.95 2R24.1
N$7
  Top 0.5: R4.1 52.6,31.9 R10.2
N$8
  Top 0.5: 2R18.2 26.8,106.2 2Q12.C
N$9
  Top 0.5: NTC.2 64.97,46.47 R6.2 64.7,43.15 Q7.1
N$10
  Top 0.5: Q7.3 63.6,40.4 64,40 67.27,40 VENT.1
N$11
  Top 1: 3R1.2 81,127 3R23.2
N$12
  Top 0.5: 3R19.2 63.25,116.1 T2.B 68.55,117.1 3Q3HV1.1
N$13
  Top 0.5: 3QH.C 80.9,109.3 2R27.1
N$17
  Top 0.5: 3QH.B 81.5,116.15
  Top 1: 81.5,116.15 3R35.2
N$18
  Top 1: 3R23.1 81.5,123.65 3R35.1 3R28.1
N$21
  Top 0.5: 3D2X1.C 3D2X2.C
N$22
  Top 0.5: 2R26.2 21.4,110.75 2Q11.1
N$24
  Top 0.5: R30.2 54,61 53,60 SP3.+
N$30
  Top 1: IC2.1 R33.1 R34.2
N$31
  Top 1: IC1.6 57.37,60.73 R30.1
N$34
  Top 1: R29.2 54.18,63.2 R31.1 54.5,63.68 R32.2
N$35
  Top 1: IC1.7 57.9,63.27 R29.1
PUMP+  (1 unrouted)
  Top 2.5: Q3.D IN+.1 Q12.D | Q14.D IN+1.1 Q4.D
  Route3 3.81: PLUS2.1 36,69 48,81 70,81 IN+.1 | PLUS1.1 36,30 27,21 27,17.92 Q14.D
  pour Top (isolate 2, rank 2): 8,120 8,106 15,106 15,120
  pour Top (isolate 2): 26,66 38,70 38,29 26,29
  pour Bottom (isolate 2): 26,66 38,70 38,29 26,29
RED  (2 unrouted)
  Top 0.5: 3C3.- 70.3,110.3 68.5,109 68.5,103.1 3D2X1.A 66.5,100.6 JP5.1
  Top 1: C5.1 61.5,19.5 64,22 64,23.42 D4.A 68.9,23.4 72,21 72,15
  Top 2.5: Q3.S 66.41,82.41 66,82 | 66,82 RED.1 | 66,82 66,77.49 Q12.S | Q1.D RED1.1 72,15 Q11.D
  Route5 3.81: Q12.S 66.41,71.59 68,70 95,70 | Q11.D 90,16 95,61
  pour Top (isolate 2, rank 2, no thermals): 65,105 70,105 70,100 65,100
SNUB2
  pour Top (isolate 2, rank 2): 3,104 15,104 15,97 3,97
V12  (via drill 0.6)  (2 unrouted)
  Top 0.5: 46,108 38,108 36.8,109.2 2JR4E.3 2JR4E1.3 28.04,109.96 28,110 28,114.6 24,114.6 24,112.2 2R24.2 23.9,110.15 2Q12.E | 46,108 49.65,108 R11.2 52.96,108.4 JP3.4 54.84,109.84 55,110 57.64,110 3JP1.4 60.86,109.84 3D3X1.A | 46,108 JP6.1
  Top 1: Q9.C 77.7,38.7 v76,37
  pour Bottom (isolate 1.5): 47,72 85,72 85,35 47,35
VDD  (via drill 0.6 pad 1.5)
  Top 0.406: v62.5,53.5 62.5,50.47 NTC.1
  Top 0.5: NTC.1 62.43,53.43 v62.5,53.5 67,53.5 71,55 3C1.+ | v64.5,33 65.3,33.7 IC2.4 IC2.2 | IC1.1 64.81,65.81 64,65 MCU.5 | v67.8,67.5 67.1,69.08 67,69 67,69.1 62.7,69.1 62.7,68.68 C2.2
  Top 1: IC2.4 64.85,32.62 R9.2 | R33.2 72.25,33.6 IC2.2 | v67.8,67.5 IC1.1
  Bottom 0.406: 67.5,53.5 68,54
  Bottom 0.5: v64.5,33 64.5,37.1 62.5,42 v62.5,53.5 67.5,53.5 | 68,54 70.4,55.9 70.4,65.9 v67.8,67.5
VIN
  Top 0.35: 75.79,43.5 75.79,42.21 77,41 77.45,41 Q9.E
  Top 0.5: VENT.2 71.73,43.27 72.25,42.75
  Top 1: L1.2 81,52 78.4,49.4 R2.2 76.8,46.8 76,46 76,44.09 FZT.3 75.79,43.5 C12.+ 72.25,42.75 73.15,42.65 IC2.3
X
  Top 0.5: Q6.3 57,35.27 BUTT.2 | R9.1 59.83,32.17 58,34 58,35.73 BUTT.2 | R12.1 57.1,36.63 BUTT.2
